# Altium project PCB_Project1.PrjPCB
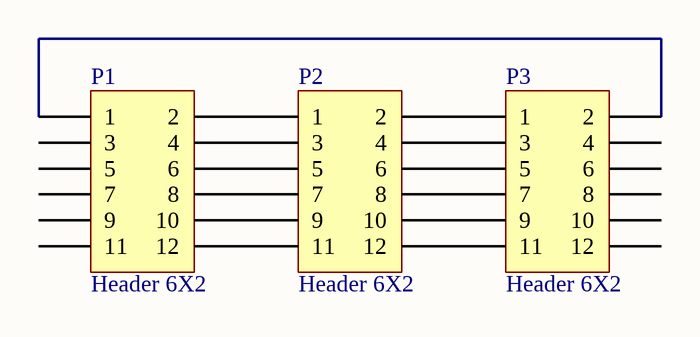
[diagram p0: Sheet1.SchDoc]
1 sheet, 3 parts. Net scope: global (net labels, ports and power ports of the same name join across sheets).
Board file: PCB1.PcbDoc

## Sheet Sheet1.SchDoc
size A

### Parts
P1  Header 6X2  [HDR2X6]
P2  Header 6X2  [HDR2X6]
P3  Header 6X2  [HDR2X6]

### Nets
NetP1_1: P1.1 P3.2
NetP1_2: P1.2 P2.1
NetP1_4: P1.4 P2.3
NetP1_6: P1.6 P2.5
NetP1_8: P1.8 P2.7
NetP1_10: P1.10 P2.9
NetP1_12: P1.12 P2.11
NetP2_2: P2.2 P3.1
NetP2_4: P2.4 P3.3
NetP2_6: P2.6 P3.5
NetP2_8: P2.8 P3.7
NetP2_10: P2.10 P3.9
NetP2_12: P2.12 P3.11

Not connected (* = marked no-connect by the designer): P1 3 5 7 9 11; P3 4 6 8 10 12

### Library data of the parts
P1-P3 = Header 6X2: Header, 6-Pin, Dual row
